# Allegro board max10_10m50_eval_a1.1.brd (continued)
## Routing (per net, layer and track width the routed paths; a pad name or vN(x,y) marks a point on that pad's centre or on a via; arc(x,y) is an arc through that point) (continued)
HDMI_VIDEO_DIN4: length 29.2
  TOP w0.147: U3.58 61.86,60.84 v2(62.36,61.34) ; U1.D12 v1(57.52,45.47)
  ART04 w0.109: v1(57.52,45.47) 57.52,45.86 57.02,46.35 57.02,46.74 57.53,47.24 57.53,53.86 57.65,53.98 59.95,53.98 60.07,54.09 60.07,54.37 59.95,54.48 57.65,54.48 57.53,54.6 57.53,54.87 57.65,54.99 60.08,54.99 60.2,55.11 60.2,61.09 61.47,62.36 62.1,62.36 62.36,62.1 v2(62.36,61.34)
HDMI_VIDEO_DIN5: length 29.6
  TOP w0.147: U3.57 60.23,61.35 59.42,60.53 59.4,60.53 58.93,60.06 58.93,56.89 59.31,56.52 60.96,56.52 61.34,56.13 61.34,54.74 62.61,53.47 65.91,53.47 66.04,53.59 66.04,54.46 66.19,54.61 66.53,54.61 66.67,54.46 66.67,53.47 67.18,52.96 67.18,50.8 66.42,50.04 61.98,50.04 61.51,49.58 61.51,47.46 U1.B16
HDMI_VIDEO_DIN6: length 29.5
  TOP w0.147: U1.A16 61.02,49.84 61.72,50.55 65.28,50.55 65.66,50.93 65.66,52.3 65.81,52.45 66.02,52.45 66.17,52.3 66.17,51.07 66.31,50.93 66.53,50.93 66.67,51.07 66.67,52.7 66.42,52.96 62.48,52.96 60.83,54.61 60.83,54.99 59.94,55.88 59.3,55.88 58.48,56.7 58.48,60.77 58.7,60.99 59.24,60.99 60.09,61.84 U3.56
HDMI_VIDEO_DIN7: length 32.6
  TOP w0.147: U1.C15 60.51,46.46 60.51,50.35 61.34,51.18 61.34,51.8 61.49,51.94 61.83,51.94 61.98,51.8 61.98,51.2 62.12,51.05 62.46,51.05 62.61,51.2 62.61,51.8 62.76,51.94 63.1,51.94 63.25,51.8 63.25,51.2 63.39,51.05 63.73,51.05 63.88,51.2 63.88,51.8 64.03,51.94 64.39,51.94 64.52,51.82 64.52,51.2 64.66,51.05 65,51.05 65.15,51.2 65.15,52.3 65,52.45 61.59,52.45 61.34,52.7 61.34,53.34 60.33,54.36 60.33,54.74 59.69,55.37 59.06,55.37 58.03,56.4 58.03,61.08 58.39,61.44 59.05,61.44 59.95,62.35 U3.55
HDMI_VIDEO_DIN8: length 28.9
  TOP w0.147: U1.B14 59.52,47.47 59.52,48.56 59.22,48.85 59.22,49.06 59.44,49.28 59.8,49.28 59.94,49.42 59.94,49.64 59.8,49.78 59.46,49.78 59.31,49.93 59.31,50.14 59.82,50.65 59.82,52.94 59.96,53.09 60.18,53.09 60.33,52.94 60.33,51.46 60.47,51.31 60.69,51.31 60.83,51.46 60.83,53.09 59.82,54.1 59.82,54.48 59.44,54.86 58.8,54.86 57.58,56.09 57.58,63.29 57.81,63.52 58.02,63.52 58.17,63.37 58.17,62.26 58.42,62 58.97,62 59.81,62.84 U3.54
HDMI_VIDEO_DIN9: length 26.5
  TOP w0.147: v2(58.8,64.14) 59.09,63.84 U3.52 ; U1.A14 v1(58.52,48.47)
  BOTTOM w0.147: v2(58.8,64.14) 56.28,64.14 56.13,63.99 56.13,63.65 56.28,63.5 57,63.5 57.15,63.35 57.15,63.01 57,62.86 56.28,62.86 56.13,62.72 56.13,62.38 56.28,62.23 57.02,62.23 57.53,61.72 58.8,61.72 58.93,61.59 58.93,61.21 58.8,61.09 58.04,61.09 57.78,60.83 57.78,49.2 v1(58.52,48.47)
HDMI_VIDEO_DIN10: length 28.4
  TOP w0.147: U1.A13 58.02,48.74 58.8,49.53 58.8,50.42 59.31,50.93 59.31,54.21 59.16,54.36 58.82,54.36 58.67,54.21 58.67,51.18 58.55,51.05 58.17,51.05 58.04,51.18 58.04,54.95 57.12,55.86 57.12,63.47 58.49,64.84 U3.50
HDMI_VIDEO_DIN11: length 30.7
  TOP w0.147: U3.49 64.08,65.35 64.26,65.53 64.26,65.79 64.14,65.91 59.94,65.91 59.44,65.41 58.29,65.41 56.67,63.78 56.67,55.6 57.52,54.75 57.52,50.43 57.67,50.28 58.15,50.28 58.29,50.14 58.29,49.84 58.15,49.69 57.67,49.69 57.52,49.55 57.52,47.47 U1.B12
HDMI_VIDEO_DIN12: length 29
  TOP w0.147: U1.A12 57.02,54.49 56.22,55.29 56.22,64.09 59.82,67.69 60.2,67.69 60.58,67.31 60.58,66.55 60.71,66.42 60.96,66.42 61.14,66.6 61.14,67.06 61.26,67.18 61.52,67.18 61.65,67.06 61.65,66.55 61.77,66.42 62.1,66.42 62.23,66.55 62.23,67.92 62.38,68.07 62.74,68.07 62.92,67.89 U3.48
HDMI_VIDEO_DIN13: length 31
  TOP w0.147: U1.C12 56.53,46.45 56.53,54.22 55.77,54.98 55.77,64.28 60.12,68.64 60.65,68.64 60.8,68.49 60.8,67.84 60.94,67.69 61.24,67.69 61.39,67.84 61.39,68.49 61.53,68.64 63.18,68.64 63.43,68.4 U3.47
HDMI_VIDEO_DIN14: length 28.8
  TOP w0.147: U1.A11 56.01,53.97 55.32,54.67 55.32,64.47 59.94,69.09 63.37,69.09 63.92,68.54 U3.46
HDMI_VIDEO_DIN15: length 31.5
  TOP w0.147: U3.45 64.43,68.67 64.38,68.72 64.38,68.72 63.56,69.54 59.75,69.54 59.48,69.28 54.86,64.66 54.86,64.28 54.86,54.36 55.52,53.7 55.52,47.46 U1.B11
HDMI_VIDEO_DIN16: length 31.8
  TOP w0.147: U3.44 64.92,68.81 64.88,68.85 64.88,68.86 64.83,68.91 64.83,68.91 63.75,69.99 59.53,69.99 54.36,64.82 54.36,54.1 55.01,53.44 U1.A10
HDMI_VIDEO_DIN17: length 27.3
  TOP w0.147: U1.C14 v1(58.52,46.47) ; v2(65.02,65.79) 65.43,66.19 U3.43
  BOTTOM w0.147: v1(58.52,46.47) 59.04,46.47 60.33,47.75 60.33,48.39 60.07,48.64 60.07,49.53 60.33,49.78 60.33,53.98 60.07,54.23 60.07,58.55 60.51,58.98 60.51,59.61 60.07,60.04 60.07,60.52 60.51,60.96 60.51,64.44 61.72,65.66 64.9,65.66 v2(65.02,65.79)
HDMI_VIDEO_DIN18: length 28.8
  TOP w0.147: v2(65.91,65.79) 65.91,66.13 65.92,66.15 U3.42 ; U1.E14 v1(59.52,44.47)
  BOTTOM w0.147: v2(65.91,65.79) 65.28,65.15 61.98,65.15 60.96,64.14 60.96,58.29 60.58,57.91 60.58,54.36 60.83,54.11 60.83,47.5 59.01,45.68 59.01,44.97 v1(59.52,44.47)
HDMI_VIDEO_DIN19: length 29.8
  TOP w0.147: U3.41 66.43,65.53 66.42,65.53 66.17,65.28 65.28,65.28 65.15,65.15 65.15,64.9 65.28,64.77 v2(65.91,64.77) ; U1.D14 v1(59.52,45.47)
  BOTTOM w0.147: v1(59.52,45.47) 60.02,45.97 60.83,45.97 61.09,46.23 61.09,47.04 61.47,47.42 61.47,54.12 61.09,54.5 61.09,57.66 61.42,58 61.42,63.84 62.23,64.64 65.79,64.64 v2(65.91,64.77)
HDMI_VIDEO_DIN20: length 30.1
  TOP w0.147: U3.40 66.92,66.01 66.93,66.01 v2(66.93,65.79) ; U1.C13 v1(57.52,46.47)
  BOTTOM w0.147: v2(66.93,65.79) 66.29,66.42 64.77,66.42 64.52,66.17 61.47,66.17 60.06,64.75 60.06,61.45 58.29,59.69 58.29,49.78 58.93,49.15 58.93,48.26 58.63,47.97 58.38,47.97 57.52,47.1 v1(57.52,46.47)
HDMI_VIDEO_DIN21: length 29.3
  TOP w0.147: U3.39 67.43,65.27 v2(66.93,64.77) ; U1.E15 v1(60.52,44.47)
  BOTTOM w0.147: v2(66.93,64.77) 66.29,64.14 62.48,64.14 61.88,63.53 61.88,57.77 61.59,57.49 61.59,54.78 62.01,54.36 62.01,45.38 61.6,44.97 61.02,44.97 v1(60.52,44.47)
HDMI_VIDEO_DIN22: length 30.2
  TOP w0.147: U1.F15 v1(60.52,43.47) ; v2(67.94,65.79) 67.92,65.81 U3.38
  ART04 w0.109: v1(60.52,43.47) 59.94,44.04 59.94,49.7 65.15,54.91 65.15,57.91 64.26,58.8 64.26,63.75 64.64,64.14 67.06,64.14 67.44,64.52 67.44,65.28 v2(67.94,65.79)
HDMI_VIDEO_DIN23: length 30.5
  TOP w0.147: v2(67.94,64.77) 68.43,65.25 U3.37 ; U1.D15 v1(60.52,45.47)
  ART04 w0.109: v2(67.94,64.77) 69.34,63.37 69.34,59.94 68.2,58.8 65.78,58.8 65.66,58.68 65.66,58.41 65.78,58.29 66.05,58.29 66.17,58.18 66.17,57.9 66.05,57.78 65.78,57.78 65.66,57.67 65.66,57.39 65.78,57.28 66.05,57.28 66.17,57.16 66.17,56.89 66.05,56.77 65.78,56.77 65.66,56.65 65.66,56.38 65.78,56.26 66.05,56.26 66.17,56.14 66.17,55.31 60.52,49.66 v1(60.52,45.47)
HDMI_VSYNC: length 31.3
  TOP w0.147: v2(62.87,53.98) 65.26,53.98 65.41,54.12 65.41,54.39 65.26,54.54 63.63,54.54 63.43,54.74 U3.2 ; U1.H14 v1(59.52,41.47)
  ART04 w0.109: v2(62.87,53.98) 63.5,53.98 64.64,55.12 64.64,57.67 64.53,57.78 64.25,57.78 64.14,57.67 64.14,55.37 63.37,54.61 62.74,54.61 62.36,54.23 62.36,52.83 59.44,49.91 59.44,45.97 59.05,45.59 59.05,41.66 59.25,41.47 v1(59.52,41.47)
I2C_MAXII_SCL: length 8.4
  TOP w0.147: v3(29.88,51.05) 30,50.93 U4.A7
  BOTTOM w0.147: R139.2 29.84,51.02 v3(29.88,51.05) 29.88,52.16 28.83,53.21 27.94,53.21 27.81,53.09 24.57,53.09 R206.1
I2C_MAXII_SDA: length 19.5
  TOP w0.147: v3(29.21,51.02) 29.5,50.73 U4.A6
  BOTTOM w0.147: R209.1 14.48,53.15 14.48,51.82 14.99,51.31 19.56,51.31 20.07,51.82 25.02,51.82 25.53,52.32 27.9,52.32 v3(29.21,51.02) 28.96,50.76 R137.2
JTAG_LOCK: length 27.6
  TOP w0.147: U4.Y8 30.23,40.7 v3(30.23,40.26) ; R151.2 v2(12.57,50.16)
  ART04 w0.109: v3(30.23,40.26) 29.59,40.26 27.81,42.04 27.81,44.45 26.42,45.85 26.16,45.85 25.91,46.1 25.91,46.86 23.62,49.15 23.62,49.4 21.97,51.05 17.02,51.05 15.49,49.53 15.49,49.15 15.11,48.77 13.72,48.77 13.34,49.15 13.34,49.4 v2(12.57,50.16)
JTAG_LOCK_R: length 9
  TOP w0.147: R151.1 5.71,50.16 4.45,48.89 J7.7
JTAG_SAFE: length 11.8
  TOP w0.147: U4.Y17 36.35,39.62 40.51,39.62 41.17,38.97 U1.K1
LPDDR2_CA0: length 19.5
  TOP w0.102: 77.6,38.34 79.33,38.34 U2.P3
  TOP w0.147: 77.6,38.34 77.36,38.34 77.09,38.61 74.95,38.61 74.8,38.46 74.8,38.12 74.95,37.97 76.81,37.97 76.96,37.83 76.96,37.49 76.81,37.34 74.68,37.34 74.17,37.85 74.17,38.35 73.28,39.24 69.09,39.24 68.37,39.97 U1.J22
LPDDR2_CA1: length 21.3
  TOP w0.102: 77.61,39.64 79.33,39.64 U2.N3
  TOP w0.137: U1.J21 66.52,40.47
  TOP w0.147: 66.52,40.47 68.75,40.47 69.47,39.75 71.99,39.75 72.14,39.9 72.14,40.24 71.99,40.39 69.74,40.39 69.6,40.53 69.6,40.87 69.74,41.02 72.39,41.02 74.34,39.07 77.04,39.07 77.61,39.64
LPDDR2_CA2: length 19.6
  TOP w0.102: U2.M3 79.33,40.29 79.33,40.83 79.23,40.94 77.6,40.94
  TOP w0.147: 77.6,40.94 77.38,41.15 75.69,41.15 74.42,42.42 74.42,46.23 73.91,46.74 72.64,46.74 71.88,45.97 70.02,45.97 U1.F22
LPDDR2_CA3: length 20.4
  TOP w0.102: U2.M2 78.68,40.29 77.75,40.29
  TOP w0.147: 77.75,40.29 76.73,40.29 76.58,40.13 75.06,40.13 73.26,41.93 73.26,43.2 72.9,43.56 72.26,43.56 72.01,43.31 70.74,43.31 70.53,43.52 70.53,43.73 70.74,43.94 71.63,43.94 71.84,44.16 71.84,44.36 71.63,44.58 70.48,44.58 67.37,41.47 66.52,41.47 U1.H21
LPDDR2_CA4: length 20.3
  TOP w0.147: U1.H22 67.64,40.97 69.47,42.8 72.52,42.8 72.64,42.67 72.64,42.31 72.5,42.16 69.62,42.16 69.47,42.02 69.47,41.68 69.62,41.53 72.77,41.53 74.68,39.62 76.83,39.62 77.17,39.96 U2.M1
LPDDR2_CA5: length 17.5
  TOP w0.102: U2.G2 78.68,42.88 77.6,42.88
  TOP w0.147: 77.6,42.88 77.13,42.88 75.44,44.58 75.44,47.88 75.18,48.13 70.18,48.13 U1.D22
LPDDR2_CA6: length 17.4
  TOP w0.102: U2.F2 78.68,43.53 77.6,43.53
  TOP w0.147: U1.C22 69.82,48.77 75.44,48.77 75.95,48.26 75.95,44.96 77.37,43.53 77.6,43.53
LPDDR2_CA7: length 20.2
  TOP w0.102: 77.6,42.09 78.11,41.59 79.23,41.59 79.33,41.69 79.33,43.53 U2.F3
  TOP w0.147: 77.6,42.09 77.27,42.42 76.93,42.42 74.93,44.41 74.93,47.24 74.68,47.5 72.39,47.5 71.63,46.74 69.79,46.74 U1.E22
LPDDR2_CA8: length 18.8
  TOP w0.102: 77.6,44.83 79.33,44.83 U2.E3
  TOP w0.147: U1.A21 67.96,49.91 76.07,49.91 76.96,49.02 76.96,45.47 77.6,44.83
LPDDR2_CA9: length 17.4
  TOP w0.102: U2.E2 78.68,44.18 77.6,44.18
  TOP w0.147: U1.B22 69.45,49.4 75.82,49.4 76.45,48.77 76.45,45.21 77.48,44.18 77.6,44.18
LPDDR2_CK: length 20.9
  TOP w0.102: U2.J3 v3(79.98,41.59)
  TOP w0.114: U1.D18 v1(63.52,44.47)
  BOTTOM w0.114: v1(63.52,44.47) 63.25,44.73 63.25,45.02 63.44,45.21 64.52,45.21 65.6,44.13 74.93,44.13 76.71,42.35 76.71,42.04 76.93,41.81 77.25,41.81 77.59,41.46 78.04,41.46 78.23,41.27 78.55,41.27 78.74,41.46 79,41.46 R33.2 79.48,41.08 v3(79.98,41.59)
LPDDR2_CKE: length 15.8
  TOP w0.147: U1.E21 v1(66.52,43.46) ; v2(75.31,42.42) 75.95,41.78 77.34,41.78 77.87,41.26 U2.K1
  BOTTOM w0.147: v1(66.52,43.46) 68.2,41.78 68.71,41.78 69.47,42.55 70.23,42.55 70.99,41.78 71.75,41.78 72.52,42.55 73.41,42.55 74.36,41.59 R31.2 75.31,41.72 v2(75.31,42.42)
LPDDR2_CKN: length 21.1
  TOP w0.102: U2.H3 v3(79.98,42.23)
  TOP w0.114: U1.E18 v1(62.52,44.46)
  BOTTOM w0.114: v3(79.98,42.23) 79.6,41.86 79.49,41.86 R33.1 79.18,41.78 77.73,41.78 75.06,44.45 65.73,44.45 64.65,45.53 63.31,45.53 62.93,45.15 62.93,44.88 v1(62.52,44.46)
LPDDR2_CSN: length 19.6
  TOP w0.147: U2.L1 75.47,40.61 73.84,42.24 73.84,45.92 73.66,46.1 73.41,46.1 73.22,45.91 73.22,44.32 73.09,44.2 72.64,44.2 72.52,44.32 72.52,44.96 72.33,45.14 70.19,45.14 U1.G22
LPDDR2_DM0: length 25.2
  TOP w0.147: U2.K5 80.23,40.54 80.23,36.83 v3(79.98,36.58) ; U1.N19 v1(64.52,35.46)
  ART04 w0.109: v1(64.52,35.46) 65.02,34.96 65.02,34.16 65.15,34.04 66.67,34.04 67.06,33.66 69.34,33.66 69.85,33.15 70.87,33.15 71.13,33.41 71.13,33.79 71.5,34.16 73.53,34.16 74.17,34.8 74.55,34.8 74.8,34.54 79.12,34.54 79.98,35.4 v3(79.98,36.58)
LPDDR2_DM1: length 27.5
  TOP w0.137: U1.J15 v1(60.52,40.47)
  TOP w0.147: U2.H5 80.5,43.01 v3(80.5,45.48)
  ART04 w0.109: v3(80.5,45.48) 80.15,45.13 77.72,45.13 77.52,45.34 68.07,45.34 66.75,44.02 66.24,44.02 66.04,43.81 66.04,43.31 65.82,43.09 64.18,43.09 63.89,42.8 63.89,42.29 63.37,41.77 63.37,41.4 62.83,40.86 62.32,40.86 61.98,40.51 61.98,40.13 61.85,40 60.98,40 v1(60.52,40.47)
LPDDR2_DQ0: length 23.7
  TOP w0.147: U1.N18 v1(63.52,35.46) ; U2.N8 v3(83.23,38.99)
  ART04 w0.109: v3(83.23,38.99) 83.23,38.53 82.8,38.1 81.79,38.1 81.03,37.34 79.63,37.34 78.11,35.81 72.9,35.81 72.39,35.31 70.61,35.31 70.23,34.92 69.85,34.92 69.47,35.31 69.09,35.31 68.71,34.92 68.33,34.92 67.82,35.43 66.08,35.43 65.67,35.84 63.89,35.84 v1(63.52,35.46)
LPDDR2_DQ1: length 24.7
  TOP w0.147: U2.M8 v3(83.23,39.64) ; U1.N20 v1(65.52,35.46)
  ART04 w0.102: 84.25,39.83 84.12,39.96 83.55,39.96 v3(83.23,39.64)
  ART04 w0.109: 84.25,39.83 84.25,38.86 82.04,36.65 81.08,36.65 80.77,36.96 79.88,36.96 78.23,35.31 73.15,35.31 72.52,34.67 71.37,34.67 70.97,34.27 67.46,34.27 66.8,34.92 66.05,34.92 v1(65.52,35.46)
LPDDR2_DQ2: length 24.2
  TOP w0.147: U2.M7 v3(82.58,39.64) ; U1.M20 v1(65.52,36.46)
  ART04 w0.109: v1(65.52,36.46) 65.94,36.46 66.31,36.09 67.69,36.09 67.88,36.28 72.1,36.28 72.73,36.92 76.54,36.92 76.71,37.08 76.71,37.34 76.83,37.46 77.09,37.46 77.22,37.34 77.22,37.04 77.34,36.92 78.06,36.92 78.21,37.06 78.21,37.23 78.11,37.34 77.72,37.34 77.6,37.46 77.6,37.97 77.72,38.1 78.11,38.1 78.23,38.23 78.23,38.51 78.36,38.63 78.61,38.63 78.74,38.51 78.74,38.1 78.87,37.97 79.12,37.97 79.25,38.1 79.25,38.51 79.38,38.63 79.63,38.63 79.76,38.51 79.76,38.35 79.86,38.25 80.16,38.25 80.26,38.35 80.26,38.61 80.39,38.73 81.28,38.73 81.41,38.86 81.41,39.12 81.51,39.22 82.17,39.22 v3(82.58,39.64)
LPDDR2_DQ3: length 27.4
  TOP w0.147: U1.M14 v1(59.52,36.46) ; U2.M9 v3(83.88,39.64)
  ART04 w0.102: 80.2,37.72 80.5,38.01 80.94,38.01 81.26,38.34 81.77,38.34 82.74,39.31 83.55,39.31 v3(83.88,39.64)
  ART04 w0.109: v1(59.52,36.46) 59.89,36.09 65.77,36.09 66.02,35.83 72.28,35.83 72.77,36.32 78.11,36.32 79.5,37.72 80.2,37.72
LPDDR2_DQ4: length 25.1
  TOP w0.147: U2.M6 v3(81.93,39.64) ; U1.M18 v1(63.52,36.46)
  ART04 w0.102: 80.9,38.99 80.01,38.99 79.64,39.36 78.48,39.36 78.1,38.99 77.72,38.99 77.34,38.61
  ART04 w0.109: v3(81.93,39.64) 81.55,39.64 80.9,38.99 ; v1(63.52,36.46) 63.05,36.46 62.94,36.58 62.94,36.83 63.07,36.96 67.69,36.96 67.94,36.7 71.88,36.7 72.01,36.83 72.01,37.21 72.52,37.72 72.86,37.72 73.24,37.34 73.41,37.34 73.53,37.46 73.53,37.85 73.62,37.93 73.95,37.93 74.04,37.85 74.04,37.46 74.17,37.34 74.42,37.34 74.55,37.46 74.55,37.85 74.64,37.93 74.97,37.93 75.06,37.85 75.06,37.46 75.18,37.34 75.44,37.34 75.82,37.72 76.45,37.72 77.34,38.61
LPDDR2_DQ5: length 26.5
  TOP w0.147: U2.L7 v3(82.58,40.29) ; U1.M15 v1(60.52,36.46)
  ART04 w0.102: 80.12,39.64 80.45,39.31 80.84,39.31 81.49,39.96 82.76,39.96 82.86,40.06 82.86,40.2 82.78,40.29 v3(82.58,40.29)
  ART04 w0.109: 80.12,39.64 77.49,39.64 76.96,39.12 76.96,38.86 76.45,38.35 72.39,38.35 71.17,37.13 67.92,37.13 67.82,37.24 62.39,37.24 62.23,37.08 62.23,36.83 62.12,36.72 61.96,36.72 61.85,36.83 61.85,36.97 61.73,37.08 61.56,37.08 60.94,36.46 v1(60.52,36.46)
LPDDR2_DQ6: length 22.9
  TOP w0.147: U2.L8 v3(83.23,40.29) ; U1.L20 v1(65.52,38.47)
  ART04 w0.102: 80.92,40.61 82.9,40.61 v3(83.23,40.29)
  ART04 w0.109: 80.92,40.61 80.9,40.64 76.83,40.64 76.2,40 75.82,40 75.69,39.88 75.31,39.88 75.18,40 74.94,40 74.56,39.62 74.3,39.62 74.17,39.75 74.17,39.95 74.04,40.08 73.79,40.08 73.66,39.95 73.66,39.75 73.53,39.62 73.28,39.62 73.15,39.75 73.15,39.96 73.04,40.08 72.77,40.08 72.64,39.95 72.64,39.75 72.52,39.62 72.26,39.62 72.14,39.75 72.14,39.95 72.01,40.08 71.75,40.08 71.63,39.95 71.63,39.75 71.5,39.62 71.25,39.62 71.12,39.75 71.12,39.95 70.99,40.08 70.74,40.08 70.61,39.95 70.61,39.75 70.48,39.62 70.23,39.62 70.1,39.75 70.1,39.88 69.98,40 69.72,40 69.47,39.75 68.96,39.75 68.1,38.89 66.34,38.89 65.91,38.47 v1(65.52,38.47)
LPDDR2_DQ7: length 24.6
  TOP w0.147: U2.L9 v3(83.88,40.29) ; U1.L18 v1(63.52,38.47)
  ART04 w0.109: v3(83.88,40.29) 84.35,40.29 84.45,40.39 84.45,40.77 84.33,40.89 83.82,40.89 83.69,40.77 83.44,40.77 83.31,40.89 81.92,40.89 81.53,41.27 80.9,41.27 80.56,40.94 79.8,40.94 79.76,40.89 76.58,40.89 76.2,40.51 69.09,40.51 67.82,39.24 66.29,39.24 65.89,38.84 64.67,38.84 64.67,38.84 64.24,38.84 63.87,38.47 v1(63.52,38.47)
LPDDR2_DQ8: length 25.1
  TOP w0.147: U1.K20 v1(65.52,39.47) ; U2.G9 v3(83.23,42.88)
  ART04 w0.102: 82.62,43.31 83.04,42.88 v3(83.23,42.88) ; 79.63,41.91 80.14,41.91 80.39,42.16 80.77,42.16 81.03,41.91 81.92,41.91 82.3,41.53 83.69,41.53 83.82,41.66 83.82,41.8 83.71,41.91 82.45,41.91 82.25,42.1 82.25,43.14
  ART04 w0.109: 82.25,43.14 82.42,43.31 82.62,43.31 ; v1(65.52,39.47) 66.05,40 67.06,40 68.58,41.53 75.95,41.53 76.16,41.74 77.17,41.74 77.32,41.59 79.31,41.59 79.63,41.91
LPDDR2_DQ9: length 25.4
  TOP w0.147: U1.K19 v1(64.52,39.47) ; U2.G8 v3(82.58,42.88)
  ART04 w0.102: 84.33,42.29 84.06,42.56 82.9,42.56 v3(82.58,42.88)
  ART04 w0.109: v1(64.52,39.47) 64.52,39.22 64.64,39.09 65.67,39.09 66.33,39.75 67.44,39.75 68.79,41.11 76.07,41.11 76.28,41.32 79.72,41.32 79.78,41.25 80.24,41.25 80.52,41.53 81.79,41.53 82.09,41.22 84.02,41.22 84.33,41.53 84.33,42.29
LPDDR2_DQ10: length 26.6
  TOP w0.147: U2.G7 v3(81.93,42.88) ; U1.K18 v1(63.52,39.47)
  ART04 w0.102: v3(81.93,42.88) 81.6,42.56 79.77,42.56 79.12,41.91 77.6,41.91
  ART04 w0.109: 77.6,41.91 77.34,42.16 75.82,42.16 75.61,41.95 74.76,41.95 74.68,42.04 74.68,42.35 74.55,42.48 74.3,42.48 74.17,42.35 74.17,42.04 74.08,41.95 73.75,41.95 73.66,42.04 73.66,42.35 73.53,42.48 73.28,42.48 73.15,42.35 73.15,42.04 73.07,41.95 72.73,41.95 72.64,42.04 72.64,42.35 72.52,42.48 72.26,42.48 72.14,42.35 72.14,42.04 72.05,41.95 71.71,41.95 71.63,42.04 71.63,42.35 71.5,42.48 71.25,42.48 71.12,42.35 71.12,42.04 71.03,41.95 70.69,41.95 70.61,42.03 70.61,42.35 70.48,42.48 70.23,42.48 70.1,42.35 70.1,42.04 70.03,41.96 69.67,41.96 69.59,42.04 69.59,42.3 69.41,42.48 68.89,42.48 66.81,40.4 66.05,40.4 65.66,40 64.52,40 64.06,39.54 64.06,39.24 63.84,39.03 63.61,39.03 63.52,39.12 v1(63.52,39.47)
LPDDR2_DQ11: length 26.1
  TOP w0.147: U1.H19 v1(64.52,41.47) ; U2.F6 v3(81.93,44.18)
  ART04 w0.102: v3(81.93,44.18) 82.14,44.18 82.27,44.31 82.27,44.45 82.14,44.58 81.03,44.58 80.9,44.45 80.9,44.2 80.77,44.07 80.52,44.07 80.39,44.2 80.39,44.45 80.26,44.58 79.76,44.58 79.63,44.45 79.63,44.2 79.5,44.07 79.38,44.07 79.25,44.2 79.25,44.45 79.12,44.58 78.97,44.58 78.87,44.48 78.87,44.2 78.74,44.07 78.59,44.07 78.49,44.17 78.49,44.48 78.38,44.58 78.23,44.58 78.11,44.45 78.11,44.29 78,44.18 77.5,44.18
  ART04 w0.109: 77.5,44.18 77.38,44.07 69.22,44.07 68.83,44.45 68.45,44.45 68.07,44.07 68.07,43.81 67.94,43.69 67.56,43.69 67.31,43.43 67.31,43.05 66.17,41.91 65.41,41.91 65.15,42.16 64.82,42.16 64.52,41.86 64.21,41.86 63.88,41.53 63.88,41.02 64.01,40.89 64.14,40.89 64.52,41.27 v1(64.52,41.47)
LPDDR2_DQ12: length 25
  TOP w0.147: U1.H20 v1(65.52,41.47) ; U2.F9 v3(83.23,43.53)
  ART04 w0.102: 77.27,43.53 78.08,43.53 78.4,43.86 82.4,43.86 83.05,43.21 84.58,43.21 84.84,43.46 84.84,44.32 84.65,44.51 84.4,44.51 84.21,44.32 84.21,43.99 84.07,43.86 83.74,43.86 83.41,43.53 v3(83.23,43.53)
  ART04 w0.109: 77.27,43.53 77.22,43.59 68.41,43.59 68.17,43.35 66.29,41.47 v1(65.52,41.47)
LPDDR2_DQ13: length 27.6
  TOP w0.147: v1(62.52,41.47) 62.52,41.46 U1.H18 ; U2.F7 v3(82.58,44.18)
  ART04 w0.102: 77.62,46.46 82.06,46.46 82.25,46.27 82.25,46 83.55,44.7 83.55,44.05 83.36,43.86 82.9,43.86 v3(82.58,44.18)
  ART04 w0.109: 77.62,46.46 68.05,46.46 66.55,44.96 65.66,44.96 64.77,44.07 64.14,44.07 62.91,42.84 62.91,41.86 v1(62.52,41.47)
LPDDR2_DQ14: length 28.7
  TOP w0.147: U1.J14 v1(59.52,40.47) ; U2.F8 v3(83.23,44.18)
  ART04 w0.102: 77.6,45.81 82.08,45.81 83.23,44.66 v3(83.23,44.18)
  ART04 w0.109: 77.6,45.81 68.03,45.81 66.68,44.45 65.76,44.45 65.15,43.84 64.36,43.84 63.14,42.62 63.14,41.56 62.67,41.09 60.49,41.09 59.86,40.47 v1(59.52,40.47)
LPDDR2_DQ15: length 27.7
  TOP w0.147: U1.J18 v1(63.52,40.47) ; U2.E8 v3(82.58,44.83)
  ART04 w0.109: v3(82.58,44.83) 82.3,44.83 82.17,44.97 82.17,45.34 82.04,45.47 81.79,45.47 81.66,45.34 81.66,44.97 81.53,44.84 77.56,44.84 77.29,44.58 76.81,44.58 76.7,44.69 76.7,44.8 76.58,44.92 76.35,44.92 76.23,44.8 76.23,44.69 76.11,44.58 75.88,44.58 75.76,44.69 75.76,44.8 75.65,44.92 75.41,44.92 75.3,44.8 75.3,44.69 75.18,44.58 74.94,44.58 74.83,44.69 74.83,44.8 74.71,44.92 74.48,44.92 74.36,44.8 74.36,44.69 74.24,44.58 74.01,44.58 73.89,44.69 73.89,44.8 73.78,44.92 73.54,44.92 73.43,44.8 73.43,44.69 73.31,44.58 73.08,44.58 72.96,44.69 72.96,44.8 72.84,44.92 72.61,44.92 72.49,44.8 72.49,44.69 72.37,44.58 72.14,44.58 72.02,44.69 72.02,44.8 71.91,44.92 71.67,44.92 71.56,44.8 71.56,44.69 71.44,44.58 71.21,44.58 71.09,44.69 71.09,44.8 70.97,44.92 70.74,44.92 70.62,44.8 70.62,44.69 70.5,44.58 70.27,44.58 70.15,44.69 70.15,44.8 70.04,44.92 69.8,44.92 69.69,44.8 69.69,44.69 69.57,44.58 69.34,44.58 69.22,44.69 69.22,44.8 69.1,44.92 68.29,44.92 66.93,43.56 66.93,43.31 66.46,42.84 64.3,42.84 64.14,42.67 64.14,42.16 63.63,41.66 63.63,41.15 63.52,41.04 v1(63.52,40.47)
LPDDR2_DQS0: length 26.6
  TOP w0.114: U2.L6 v3(81.28,40.29) ; U1.L14 v1(59.52,38.47)
  ART04 w0.084: v3(81.28,40.29) 80.95,39.96 77.17,39.96 76.07,38.86 71.66,38.86 71.5,38.7 71.5,38.35 71.12,37.97 70.48,37.97 70.1,38.35 70.1,38.7 69.98,38.82 69.05,38.82 67.82,37.59 61.5,37.59 60.82,36.91 60.12,36.91 59.82,37.21 59.82,38.16 v1(59.52,38.47)
LPDDR2_DQS0N: length 26.5
  TOP w0.114: U2.L5 v3(80.63,40.29) ; U1.L15 v1(60.52,38.47)
  ART04 w0.084: v3(80.63,40.29) 77.08,40.29 75.95,39.15 75.56,39.15 75.35,39.37 75.06,39.37 74.84,39.15 71.54,39.15 71.21,38.82 71.21,38.48 71,38.27 70.61,38.27 70.4,38.48 70.4,38.82 70.1,39.12 68.93,39.12 67.7,37.88 66.67,37.88 66.46,38.1 66.17,38.1 65.95,37.88 65.6,37.88 65.38,38.1 65.11,38.1 64.9,37.88 64.52,37.88 64.3,38.1 64.01,38.1 63.79,37.88 63.41,37.88 63.19,38.1 62.99,38.1 62.78,37.88 62.36,37.88 62.14,38.1 61.85,38.1 61.63,37.88 61.38,37.88 60.7,37.2 60.24,37.2 60.11,37.33 60.11,38.06 v1(60.52,38.47)
LPDDR2_DQS1: length 26.6
  TOP w0.114: U1.K14 v1(59.52,39.47) ; U2.G6 v3(81.93,43.53)
  ART04 w0.084: v3(81.93,43.53) 81.6,43.21 79.91,43.21 79.5,42.8 79.09,42.8 78.82,43.07 78.55,43.07 78.07,42.58 76.71,42.58 76.41,42.89 68.7,42.89 66.65,40.84 64.91,40.84 63.92,39.84 63.28,39.84 63.14,39.7 63.14,39.04 62.94,38.85 60.13,38.85 v1(59.52,39.47)
LPDDR2_DQS1N: length 26.9
  TOP w0.114: U1.K15 v1(60.52,39.47) ; U2.G5 v3(81.28,43.53)
  ART04 w0.084: v3(81.28,43.53) 81.24,43.5 79.79,43.5 79.38,43.09 79.21,43.09 78.94,43.36 78.43,43.36 77.95,42.88 76.83,42.88 76.53,43.18 68.58,43.18 66.49,41.09 64.75,41.09 63.75,40.09 63.17,40.09 62.89,39.81 62.89,39.19 62.8,39.09 62.25,39.09 62.1,39.24 61.85,39.24 61.7,39.09 61.36,39.09 61.21,39.24 60.86,39.24 60.71,39.09 60.25,39.09 59.94,39.4 59.94,39.75 60.07,39.88 60.39,39.88 60.52,39.75 v1(60.52,39.47)
LPDDR2_VREFCA: length 6.4
  TOP w0.305: U2.G3 80.14,43.69 80.14,44.03 v3(79.98,44.18)
  BOTTOM w0.406: R29.1 C241.2 R32.2 C10.1 79.38,45.78 79.38,44.79 v3(79.98,44.18)
LPDDR2_VREFDQ: length 4
  TOP w0.305: U2.J9 v3(83.88,42.23)
  BOTTOM w0.406: C242.2 85.98,41.34 85.92,41.27 R34.2 85.47,41.34 R30.1 C11.1 84.57,42.23 v3(83.88,42.23)
LPDDR2_ZQ: length 1.5
  TOP w0.305: U2.D3 v3(79.98,45.48)
  BOTTOM w0.305: v3(79.98,45.48) 79.98,45.12 80.26,44.83 R35.1
MAX10_BYPASSN: length 14.2
  TOP w0.147: v3(37.08,50.67) 37.08,50.25 36.8,49.97 U4.B20 ; SW2.5 45.72,53.72 46.23,53.21 R192.2 46.16,52.07 v2(44.96,52.07)
  ART04 w0.109: v3(37.08,50.67) 37.59,51.18 44.07,51.18 v2(44.96,52.07)
MAX10_CONF_DONE: length 31.6
  TOP w0.147: U4.U13 33,42.78 33.15,42.93 33.15,43.43 33.4,43.69 v3(33.91,43.69) ; U1.F8 v1(52.51,43.47)
  ART04 w0.102: 37.34,42.67 36.58,42.67
  ART04 w0.109: 36.58,42.67 35.05,44.2 34.42,44.2 v3(33.91,43.69) ; 37.34,42.67 41.66,42.67 42.29,42.04 44.07,42.04 45.85,40.26 48.66,40.26 49.26,40.86 49.69,40.86 49.78,40.77 50.16,40.77 50.29,40.89 50.55,40.89 50.89,41.24 50.89,42.76 51.05,42.93 51.53,42.93 52.07,43.47 v1(52.51,43.47)
  BOTTOM w0.147: R28.2 51,47.74 51,45.14 51.18,44.96 51.82,44.96 52.01,44.76 52.01,43.97 v1(52.51,43.47)
MAX10_CONFIG_SEL: length 25.3
  TOP w0.147: SW2.6 45.09,56.52 44.7,56.13 44.7,53.21 v2(44.32,52.83) 44.2,52.7 R191.2 ; U1.H10 v1(54.51,40.47)
  BOTTOM w0.102: 49.15,46.86 49.15,44.33 49.41,44.07 49.63,44.07 50.04,43.66 50.04,42.42 50.64,41.82 52.9,41.82 54.08,40.64 54.34,40.64 v1(54.51,40.47)
  BOTTOM w0.147: 49.15,46.86 49.15,46.99 49.02,47.12 49.02,49.02 47.2,50.84 45.43,50.84 44.32,51.94 v2(44.32,52.83)
MAX10_JTAG_TCK: length 22
  TOP w0.147: v3(35.56,51.56) 35.09,51.56 U4.A15 ; U1.G2 47.51,42.46 v1(47.51,42.47)
  BOTTOM w0.147: v3(35.56,51.56) 37.97,51.56 38.35,51.18 42.93,51.18 43.94,50.16 43.94,47.62 45.21,46.35 45.21,42.8 45.4,42.61 R23.2 46.67,42.61 46.82,42.47 v1(47.51,42.47)
MAX10_JTAG_TDI: length 27
  TOP w0.147: U4.A13 33,50.65 v3(33.78,51.43) ; U1.L4 v1(48.51,38.47)
  BOTTOM w0.147: v3(33.78,51.43) 36.7,48.51 36.7,44.32 38.48,42.55 38.48,40.26 38.73,40 41.02,40 41.27,40.26 42.8,40.26 42.99,40.07 R25.2 46.86,39.62 47.12,39.88 47.75,39.88 48.01,39.62 48.01,39.37 48.39,38.99 48.39,38.59 v1(48.51,38.47)
MAX10_JTAG_TDO: length 20.1
  TOP w0.147: U4.A12 32.5,50.79 v3(33.15,51.43)
  BOTTOM w0.147: v3(33.15,51.43) 33.15,51.18 36.07,48.26 36.07,42.04 37.21,40.89 37.21,39.5 37.97,38.73 41.53,38.73 41.66,38.61 R314.1
MAX10_JTAG_TDO_3V3: length 9.9
  TOP w0.147: U1.M5 v1(50.51,36.47)
  BOTTOM w0.147: v1(50.51,36.47) 50.02,36.96 48.77,36.96 48.01,37.72 48.01,38.58 47.73,38.86 46.99,38.86 46.86,38.99 44.32,38.99 43.94,38.61 R314.2
MAX10_JTAG_TMS: length 20.6
  TOP w0.147: U4.A16 34.83,50.8 35.56,50.8 35.81,51.05 v3(36.32,51.05) ; U1.H2 46.51,41.47 43.12,41.47 v2(43.05,41.53)
  BOTTOM w0.147: v3(36.32,51.05) 37.19,51.05 38.1,50.14 38.1,48.77 38.35,48.51 38.35,44.7 40.26,42.8 41.78,42.8 42.35,42.23 R24.2 42.93,41.4 v2(43.05,41.53)
MAX10_JTAGEN: length 31.4
  TOP w0.147: v1(52.53,38.48) 53.53,38.48 U1.K9 ; U4.A14 33.5,50.52 v3(34.42,51.43)
  BOTTOM w0.147: v3(34.42,51.43) 34.8,51.43 36.39,49.85 37.27,49.85 37.47,49.66 37.47,44.7 39.12,43.05 39.12,40.77 39.31,40.58 R21.2 R22.2 40.96,40.58 41.15,40.77 43.37,40.77 43.88,40.26 46.35,40.26 46.48,40.39 48.77,40.39 49.16,39.99 51.7,39.99 52.07,39.62 52.07,38.94 v1(52.53,38.48)
MAX10_NCONFIG: length 58.5
  TOP w0.147: U1.H9 v1(54.51,41.47) ; S6.3 45.72,17.63 45.47,17.38 42.06,17.38 41.81,17.63 S6.4 38.86,18.32 38.86,19.18 37.85,20.19 37.85,20.83 36.45,22.23 33.15,22.23 v1(32.64,22.73)
  ART04 w0.109: v1(32.64,22.73) 33.4,22.73 36.07,25.4 36.07,38.86 36.96,39.75 44.96,39.75 45.21,39.5 46.61,39.5 47.03,39.07 51.77,39.07 52.07,39.37 52.07,39.75 53.78,41.47 v1(54.51,41.47)
  BOTTOM w0.147: R203.2 56.07,41.59 55.7,41.97 55.01,41.97 v1(54.51,41.47)
MAX10_NSTATUS: length 31.4
  TOP w0.147: U1.G9 v1(53.51,42.47) ; v3(34.54,43.31) 34.54,42.8 34.5,42.76 U4.U16
  ART04 w0.109: v3(34.54,43.31) 37.59,40.26 45.34,40.26 45.76,39.84 51.53,39.84 53.51,41.83 v1(53.51,42.47)
  BOTTOM w0.147: R27.2 51.56,48.07 51.56,46.23 52.07,45.72 52.07,45.21 52.32,44.96 52.83,44.96 52.96,44.83 52.96,44.07 53.09,43.94 53.72,43.94 53.98,43.69 53.98,42.93 v1(53.51,42.47)
MAX10_RDN: length 3.6
  TOP w0.147: U1.U17 v1(62.52,32.46)
  BOTTOM w0.147: R8.2 62.17,30.99 62.74,30.99 62.99,31.24 62.99,31.99 v1(62.52,32.46)
MAX10_RESETN: length 69.2
  TOP w0.147: v2(29.72,22.1) 29.27,22.1 R204.2 28.77,21.15 29.21,20.7 29.21,19.81 29.9,19.12 S7.4 29.9,17.38 31.9,17.38 32.77,16.51 35.43,16.51 36.55,17.63 S7.3 ; v1(54.51,45.47) 54.51,45.46 U1.D9
  ART04 w0.109: v1(54.51,45.47) 54.99,44.99 54.99,44.2 54.64,43.84 52.17,43.84 51.94,44.07 50.42,44.07 50.04,43.69 50.04,41.46 49.67,41.09 49.33,41.09 49.15,41.27 48.9,41.27 48.26,40.64 46.1,40.64 44.2,42.55 42.42,42.55 41.78,43.18 37.97,43.18 36.32,44.83 33.91,44.83 33.15,44.07 33.15,43.05 35.56,40.64 35.56,35.43 34.54,34.42 34.54,25.27 32.26,22.99 30.61,22.99 v2(29.72,22.1)
MAX10_RUP: length 5.6
  TOP w0.147: U1.U18 v1(63.52,31.46)
  BOTTOM w0.147: v1(63.52,31.46) 64.01,31.96 64.01,32.77 64.2,32.96 67.06,32.96 R7.2
MAX_SDA: length 1.8
  TOP w0.147: U4.C1 26.48,49.47 v3(26.42,49.53)
  BOTTOM w0.147: v3(26.42,49.53) 26.86,49.09 R123.2
MAXII_CONF_DONE: length 3.7
  TOP w0.147: D8.2 30.58,37.77 31.12,38.31 31.12,40.26 31.5,40.64 U4.Y10
MAXII_CONF_DONE_R: length 1.3
  TOP w0.147: R194.2 D8.1
MIPI_TX_CLK24MHZ: length 72
  ART04 w0.109: v2(3.81,58.8) 3.81,46.99 6.73,44.07 7.24,44.07 9.78,41.53 9.78,37.59 14.35,33.02 14.35,26.03 14.99,25.4 17.14,25.4 17.4,25.15 19.69,25.15 20.96,23.88 22.48,23.88 23.37,24.77 25.4,24.77 26.29,23.88 26.29,21.46 26.67,21.08 v2(29.72,21.08)
  BOTTOM w0.147: R212.2 13.46,56.32 13.46,57.02 12.06,58.42 4.19,58.42 v2(3.81,58.8) ; v2(29.72,21.08) 29.72,21.44 29.93,21.65 J1.11
MIPI_TX_CLK24MHZ_R: length 1.9
  BOTTOM w0.147: R212.1 16.39,54.74 16.65,55 U14.21
MIPI_TX_CLK_HS_N: length 6.3
  TOP w0.132: R42.2 41.92,32.46 42.09,32.46 TP10.1 42.87,32.33 43.12,32.33 43.56,32.77 43.56,33.55 44.04,34.03 44.83,34.03 44.95,33.91 45.22,33.91 45.34,34.03 45.95,34.03 U1.R1
MIPI_TX_CLK_HS_P: length 7
  TOP w0.132: U1.R2 46.51,34.46 43.86,34.46 43.12,33.73 43.12,32.95 42.94,32.77 42.67,32.77 TP8.1 R41.2
MIPI_TX_CLK_LP_N: length 9.6
  TOP w0.147: U1.Y1 v1(45.51,28.46)
  BOTTOM w0.147: R47.2 TP11.1 42.8,31.75 42.8,30.86 43.81,29.84 43.81,28.83 44.32,28.32 44.68,28.32 44.83,28.47 44.83,28.7 44.43,29.11 44.43,29.31 44.6,29.49 44.94,29.49 45.51,28.91 v1(45.51,28.46)
MIPI_TX_CLK_LP_P: length 9.8
  TOP w0.147: U1.Y2 v1(46.51,28.46)
  BOTTOM w0.147: v1(46.51,28.46) 46.51,28.1 46.35,27.94 46.1,27.94 46,28.04 46,29.44 45.34,30.1 44.45,30.1 43.31,31.24 43.31,32.46 42.87,32.89 TP7.1 R37.2
MIPI_TX_CLKN: length 17.4
  TOP w0.132: v1(32.51,28.83) 32.61,28.93 33.07,28.93 33.55,28.45 34.42,28.45 35.05,29.08 35.05,31.12 35.94,32 35.94,33.29 36.3,33.66 37.36,33.66 38.81,32.2 39.3,32.2 v1(39.62,31.88) 39.99,32.24 40.34,32.24 R42.1
  BOTTOM w0.132: R43.2 38.9,32.23 39.27,32.23 v1(39.62,31.88) 39.98,32.23 40.35,32.23 R42.1 ; J1.25 31.16,28.83 v1(32.51,28.83)
MIPI_TX_CLKP: length 17.4
  TOP w0.132: R41.1 40.36,32.68 39.96,32.68 v1(39.62,33.02) 39.24,32.64 38.99,32.64 37.54,34.09 36.12,34.09 35.5,33.47 35.5,32.18 34.62,31.3 34.62,29.26 34.24,28.88 33.73,28.88 33.25,29.36 32.61,29.36 v1(32.51,29.46)
  BOTTOM w0.132: R41.1 40.35,32.67 39.98,32.67 v1(39.62,33.02) 39.27,32.67 38.9,32.67 R38.1 ; J1.26 33.54,28.91 33.07,28.91 v1(32.51,29.46)
MIPI_TX_CMOS_RST_1V8: length 22.5
  TOP w0.147: U1.T3 47.52,33.46 v1(47.51,33.46)
  ART04 w0.109: v2(42.29,21.46) 42.29,29.84 45.91,33.46 v1(47.51,33.46)
  BOTTOM w0.147: v2(42.29,21.46) R308.2 40.83,21.91 40.45,22.29 R312.2
MIPI_TX_CMOS_RST_3V3: length 57.3
  TOP w0.147: U1.B10 v1(55.52,46.46)
  ART04 w0.109: v3(32.64,51.43) 33.15,50.93 35.56,50.93 36.2,50.29 47.12,50.29 48.77,51.94 50.67,51.94 v2(50.93,51.69)
  BOTTOM w0.147: R309.2 32.7,51.82 32.64,51.75 v3(32.64,51.43) 32.64,50.8 35.43,48.01 35.43,43.43 34.42,42.42 34.42,37.59 36.32,35.69 36.32,26.42 35.88,25.97 R313.2 ; v2(50.93,51.69) 51.56,51.69 53.47,49.78 53.47,49.15 55.52,47.1 v1(55.52,46.46)
MIPI_TX_CMOS_RST_IO: length 4.9
  BOTTOM w0.147: J1.14 35.56,23.15 35.59,23.18 R312.1 36.7,23.68 C28.1 36.77,24.33 R313.1
MIPI_TX_CMOS_SCLK: length 4.7
  BOTTOM w0.147: R294.1 37.78,21.46 37.72,21.4 R302.1 37.02,21.59 35.43,21.59 34.87,22.15 J1.12
MIPI_TX_CMOS_SCLK_1V8: length 22.6
  TOP w0.147: U1.N3 v1(47.51,36.46)
  ART04 w0.109: v1(47.51,36.46) 46.99,35.94 46.99,35.31 41.66,29.97 41.66,22.48 v2(38.99,19.81)
  BOTTOM w0.147: v2(38.99,19.81) 39.05,19.88 R68.2 R294.2
MIPI_TX_CMOS_SCLK_3V3: length 40.2
  TOP w0.147: U1.J11 v1(55.51,39.46)
  ART04 w0.109: v1(55.51,39.46) 55.04,38.99 53.59,38.99 52.69,38.09 46.62,38.09 45.97,38.73 37.34,38.73 36.96,38.35 36.96,36.58 37.59,35.94 37.59,22.1 v2(36.45,20.95)
  BOTTOM w0.147: R303.2 R302.2 36.89,20.51 v2(36.45,20.95)
MIPI_TX_CMOS_SDATA: length 3.5
  BOTTOM w0.147: R304.1 R307.1 29.57,22.65 J1.13
MIPI_TX_CMOS_SDATA_1V8: length 32.1
  TOP w0.147: U1.N2 v1(46.51,35.46)
  ART04 w0.109: v1(46.51,35.46) 45.88,35.46 40.89,30.48 40.89,22.86 37.85,19.81 35.84,19.81 35.33,20.32 34.92,20.32 34.16,19.56 29.21,19.56 v2(28.7,20.07)
  BOTTOM w0.147: R307.2 v2(28.7,20.07) 28.7,19.57 28.64,19.5 R305.2
MIPI_TX_CMOS_SDATA_3V3: length 48.4
  TOP w0.147: v1(56.51,40.47) 56.52,40.47 U1.H12
  ART04 w0.109: v1(56.51,40.47) 56.05,40 53.21,40 52.96,39.75 52.96,39.24 52.7,38.99 52.2,38.99 52.05,38.84 46.5,38.84 46.23,39.12 44.45,39.12 44.32,39.24 37.08,39.24 36.45,38.61 36.45,24.89 33.15,21.59 v2(26.92,21.59)
  BOTTOM w0.147: v2(26.92,21.59) R306.2 R304.2
MIPI_TX_DATA1N: length 17
  TOP w0.132: v1(32.51,30.48) 32.61,30.58 33.12,30.58 33.53,30.99 33.53,31.62 34.29,32.38 34.29,33.13 33.53,33.89 33.53,34.42 34.01,34.9 39.27,34.9 v1(39.62,34.54) 39.98,34.9 40.35,34.9 R54.1
  BOTTOM w0.132: J1.28 33.61,29.97 32.79,29.97 32.51,30.25 v1(32.51,30.48) ; R55.2 38.97,34.85 39.32,34.85 v1(39.62,34.54) 39.98,34.9 40.35,34.9 R54.1
MIPI_TX_DATA1P: length 17
  TOP w0.132: v1(32.51,31.12) 32.61,31.02 32.94,31.02 33.09,31.17 33.09,31.8 33.85,32.57 33.85,32.95 33.09,33.71 33.09,34.6 33.83,35.33 39.27,35.33 v1(39.62,35.69) 39.98,35.33 40.35,35.33 R50.1
  BOTTOM w0.132: R51.1 38.82,35.28 39.22,35.28 v1(39.62,35.69) 39.98,35.33 40.35,35.33 R50.1 ; v1(32.51,31.12) 32.05,30.65 J1.29
MIPI_TX_DATA2N: length 15.2
  TOP w0.132: v1(32.51,27.05) 32.61,27.15 35.79,27.15 36.45,27.81 36.45,29.61 37.32,30.48 37.98,30.48 38.81,29.65 39.18,29.65 v1(39.62,29.21) 39.98,29.56 40.36,29.56 40.58,29.34 R65.1
  BOTTOM w0.132: R66.2 38.9,29.56 39.27,29.56 v1(39.62,29.21) 39.98,29.56 40.35,29.56 R65.1 ; J1.22 33.6,27.33 32.79,27.33 v1(32.51,27.05)
MIPI_TX_DATA2P: length 15.2
  TOP w0.132: v1(32.51,27.69) 32.61,27.59 35.61,27.59 36.01,27.99 36.01,29.79 37.14,30.92 38.16,30.92 38.99,30.09 39.36,30.09 v1(39.62,30.35) 39.98,30 40.36,30 40.58,30.22 R62.1
  BOTTOM w0.132: J1.23 32.48,27.65 v1(32.51,27.69) ; R63.1 38.9,30 39.27,30 v1(39.62,30.35) 39.98,30 40.35,30 R62.1
MIPI_TX_DATA3N: length 13.8
  TOP w0.132: R44.1 40.4,27.38 39.93,27.38 v1(39.62,27.69) 39.29,27.36 38.66,27.36 38.17,26.87 38.17,26.09 37.92,25.84 37.65,25.84 37.29,26.19 32.61,26.19 v1(32.51,26.29)
  BOTTOM w0.132: R45.2 38.9,27.33 39.27,27.33 v1(39.62,27.69) 39.98,27.33 40.35,27.33 R44.1 ; J1.19 31.87,25.65 v1(32.51,26.29)
MIPI_TX_DATA3P: length 13.9
  TOP w0.132: R40.1 40.3,26.95 40.03,26.95 v1(39.62,26.54) 39.25,26.92 38.84,26.92 38.61,26.69 38.61,25.91 38.1,25.4 37.47,25.4 37.11,25.75 32.61,25.75 v1(32.51,25.65)
  BOTTOM w0.132: v1(32.51,25.65) 33.27,26.42 33.52,26.42 J1.20 ; R40.1 40.35,26.9 39.98,26.9 v1(39.62,26.54) 39.27,26.9 38.9,26.9 R39.1
MIPI_TX_DATA4N: length 12.5
  TOP w0.132: v1(32.51,24) 32.61,24.1 38.61,24.1 38.79,24.28 39.22,24.28 v1(39.62,23.88) 39.95,24.2 40.38,24.2 R56.1
  BOTTOM w0.132: R56.1 40.35,24.23 39.98,24.23 v1(39.62,23.88) 39.27,24.23 38.9,24.23 R57.2 ; v1(32.51,24) 32.89,24.38 33.55,24.38 J1.16
MIPI_TX_DATA4P: length 12.5
  TOP w0.132: R53.1 40.32,24.64 40.01,24.64 v1(39.62,25.02) 39.32,24.72 38.6,24.72 38.43,24.54 32.61,24.54 v1(32.51,24.64)
  BOTTOM w0.132: R52.1 38.9,24.67 39.27,24.67 v1(39.62,25.02) 39.98,24.67 40.35,24.67 R53.1 ; v1(32.51,24.64) 31,24.64 J1.17
MIPI_TX_DATA_HS_N1: length 6.7
  TOP w0.132: R54.2 41.66,34.87 42.35,34.87 TP15.1 42.72,34.85 43.25,34.85 43.69,35.28 43.69,36.07 43.94,36.32 44.45,36.32 44.78,36 44.78,35.49 45.3,34.96 U1.P1
MIPI_TX_DATA_HS_N2: length 8.3
  TOP w0.132: U1.T1 46.01,32.59 45.81,32.38 45.59,32.38 45.47,32.51 45.47,32.91 45.35,33.03 44.84,33.03 44.58,32.77 44.58,32 43.56,30.99 43.56,29.97 43.15,29.56 42.77,29.56 TP21.1 42.24,29.64 41.77,29.64 R65.2
MIPI_TX_DATA_HS_N3: length 8
  TOP w0.132: R44.2 41.74,27.28 42.27,27.28 TP27.1 42.77,27.33 43.08,27.33 43.51,27.76 43.51,29.14 44.27,29.9 44.27,30.66 45.18,31.57 45.62,31.57 U1.U1
MIPI_TX_DATA_HS_N4: length 9.7
  TOP w0.132: U1.W1 46.37,29.96 46.46,29.88 46.46,29.59 46.33,29.46 45.81,29.46 45.06,28.71 45.06,27.03 43.62,25.58 43.62,24.81 43.06,24.26 42.8,24.26 TP33.1 42.32,24.23 41.69,24.23 R56.2
MIPI_TX_DATA_HS_P1: length 7.2
  TOP w0.132: R50.2 41.72,35.31 42.29,35.31 TP14.1 42.82,35.29 43.07,35.29 43.25,35.46 43.25,36.25 43.76,36.76 44.63,36.76 45.21,36.18 45.21,35.67 45.48,35.4 45.71,35.4 46.01,35.71 U1.N1
MIPI_TX_DATA_HS_P2: length 8.5
  TOP w0.132: U1.T2 46.51,33.46 44.66,33.46 44.14,32.95 44.14,32.18 43.12,31.17 43.12,30.15 42.97,30 42.77,30 TP20.1 42.4,30.08 41.62,30.08 R62.2
MIPI_TX_DATA_HS_P3: length 7.9
  TOP w0.132: R40.2 41.64,26.85 42.37,26.85 TP26.1 42.77,26.9 43.26,26.9 43.94,27.58 43.94,28.96 44.7,29.72 44.7,30.48 45.36,31.14 45.84,31.14 U1.V1
MIPI_TX_DATA_HS_P4: length 10.1
  TOP w0.132: R53.2 41.69,24.67 42.32,24.67 TP32.1 42.74,24.69 42.88,24.69 43.18,24.99 43.18,25.76 44.62,27.21 44.62,28.86 45.47,29.7 45.47,30.16 45.77,30.46 46.51,30.46 U1.W2
MIPI_TX_DATA_LP_N1: length 14.1
  TOP w0.147: U1.V4 v1(49.52,30.46)
  BOTTOM w0.147: R58.2 TP16.1 42.8,34.42 42.8,33.78 43.05,33.53 43.56,33.53 43.81,33.27 43.81,31.5 44.58,30.73 45.59,30.73 46.23,30.1 46.61,30.1 46.74,30.23 46.74,30.73 46.97,30.97 49.91,30.97 50.04,30.84 50.04,30.63 49.88,30.46 v1(49.52,30.46)
MIPI_TX_DATA_LP_N2: length 8.9
  TOP w0.147: U1.AB2 v1(46.52,26.47)
  BOTTOM w0.147: v1(46.52,26.47) 45.85,25.8 45.85,25.53 45.59,25.27 45.21,25.27 44.96,25.53 44.96,26.03 42.8,28.19 42.8,29.08 TP22.1 R67.1
MIPI_TX_DATA_LP_N3: length 11
  TOP w0.147: U1.AA5 49.51,27.46 49.51,26.65 48.26,25.4 44.7,25.4 v1(44.45,25.65)
  BOTTOM w0.147: v1(44.45,25.65) TP28.1 R46.2
MIPI_TX_DATA_LP_N4: length 11.2
  TOP w0.147: U1.AB6 50.7,26.65 50.7,26.32 48.64,24.26 44.32,24.26 v1(43.81,23.75)
  BOTTOM w0.147: R59.2 TP34.1 43.56,24 v1(43.81,23.75)
MIPI_TX_DATA_LP_P1: length 13.8
  TOP w0.147: U1.V5 v1(49.51,31.46)
  BOTTOM w0.147: v1(49.51,31.46) 49.01,31.97 47.21,31.97 46.61,31.37 44.96,31.37 44.83,31.5 44.83,31.88 44.96,32 45.7,32 45.85,32.15 45.85,32.49 45.7,32.64 44.7,32.64 44.45,32.89 44.45,33.66 TP13.1 R48.2
MIPI_TX_DATA_LP_P2: length 9.3
  TOP w0.147: U1.AB3 v1(47.51,26.46)
  BOTTOM w0.147: R60.2 TP19.1 43.31,29.46 43.31,28.45 44.83,26.92 45.09,26.92 45.59,27.43 45.85,27.43 46.31,26.97 47.01,26.97 v1(47.51,26.46)
MIPI_TX_DATA_LP_P3: length 11
  TOP w0.147: v1(44.45,24.77) 48.39,24.77 50.01,26.39 U1.AB5
  BOTTOM w0.147: R36.2 TP25.1 42.93,26.29 42.93,25.53 43.18,25.27 43.94,25.27 v1(44.45,24.77)
MIPI_TX_DATA_LP_P4: length 12.4
  TOP w0.147: U1.AB7 48.8,23.75 v1(44.45,23.75)
  BOTTOM w0.147: v1(44.45,23.75) 44.45,23.88 43.81,24.51 42.93,24.51 TP31.1 R49.2
MIPI_TX_GPIO1: length 23.1
  TOP w0.147: v1(47.51,32.46) 47.52,32.46 U1.U3
  ART04 w0.109: v2(39.37,18.8) 40.39,18.8 42.93,21.34 42.93,29.59 46.23,32.89 47.09,32.89 v1(47.51,32.46)
  BOTTOM w0.147: R273.1 37.02,18.73 37.47,18.29 38.86,18.29 v2(39.37,18.8)
MIPI_TX_GPIO1_IO: length 3.3
  BOTTOM w0.147: J1.10 34.86,21.15 36.13,19.88 R273.2
MIPI_TX_GPIO2: length 29.7
  TOP w0.147: R274.1 31.43,18.61 32.89,17.14 v2(35.18,17.14) ; U1.U2 v1(46.51,32.47)
  ART04 w0.109: v1(46.51,32.47) 45.09,31.04 45.09,27.43 45.97,26.54 45.97,23.75 39.37,17.14 v2(35.18,17.14)
MIPI_TX_GPIO2_IO: length 2.3
  TOP w0.147: R274.2 v2(29.72,20.07)
  BOTTOM w0.147: v2(29.72,20.07) 30.3,20.65 J1.9
MIPI_TX_GPIO3: length 35.7
  TOP w0.147: U1.U4 v1(48.51,31.46)
  ART04 w0.109: v1(48.51,31.46) 48.01,30.96 48.01,27.94 48.51,27.43 48.51,23.11 40.51,15.11 29.97,15.11 28.96,14.1 v2(28.32,14.1)
  BOTTOM w0.147: R275.1 27.3,15.49 27.94,14.86 27.94,14.48 v2(28.32,14.1)
MIPI_TX_GPIO3_IO: length 5.7
  BOTTOM w0.147: R275.2 28.57,16.83 29.34,17.59 29.34,18.96 30.02,19.65 J1.7
MIPI_TX_GPIO4: length 27.9
  TOP w0.147: U1.U5 49.52,32.46 v1(48.51,32.46)
  ART04 w0.109: v2(36.32,16) 36.83,16.51 39.62,16.51 46.99,23.88 46.99,28.7 46.48,29.21 46.48,31.37 46.99,31.88 47.93,31.88 v1(48.51,32.46)
  BOTTOM w0.147: R276.1 37.02,16.7 v2(36.32,16)
MIPI_TX_GPIO4_IO: length 3.2
  BOTTOM w0.147: R276.2 36.13,18.35 35.33,19.15 J1.6
MIPI_TX_GPIO5: length 33.6
  TOP w0.147: U1.V3 48.01,30.97 v1(47.52,31.47)
  ART04 w0.109: v1(47.52,31.47) 47.52,31.13 46.99,30.61 46.99,29.97 47.5,29.46 47.5,27.56 48.01,27.05 48.01,24 45.09,21.08 45.09,20.19 40.39,15.49 34.92,15.49 33.91,16.51 30.23,16.51 v2(29.59,15.88)
  BOTTOM w0.147: v2(29.59,15.88) 29.59,15.37 29.27,15.05 R277.1
MIPI_TX_GPIO5_IO: length 4.3
  BOTTOM w0.147: J1.5 29.99,18.65 29.72,18.38 29.72,17.08 R277.2
OV5640_CAM_PWRON: length 82
  TOP w0.137: v2(52.58,9.65) 52.68,9.76 J3.11
  TOP w0.147: U1.L2 46.51,38.47 40.91,38.47 40.13,39.24 35.94,39.24 35.18,38.48 34.42,38.48 31.11,35.18 31.11,33.4 30.48,32.77 30.48,29.97 29.72,29.21 v2(29.34,29.21)
  ART04 w0.109: v2(26.04,13.46) 26.92,12.57 29.21,12.57 30.61,13.97 40.89,13.97 44.58,17.65 44.83,17.65 v2(45.09,17.91)
  BOTTOM w0.147: v2(45.09,17.91) 45.6,17.91 45.85,17.66 45.85,16.76 48.64,13.97 52.07,13.97 53.44,12.6 53.44,11.53 52.58,10.67 v2(52.58,9.65) 51.7,9.65 C38.1 R98.2 ; v2(29.34,29.21) 28.83,28.7 28.83,26.54 25.53,23.24 25.53,13.97 v2(26.04,13.46)
OV5640_CAM_RESETB: length 35.1
  TOP w0.147: J3.15 54.68,11.86 54.61,11.94 v2(54.61,12.32) ; U1.M4 v1(48.51,36.46)
  ART04 w0.109: v2(47.5,19.43) 48.9,20.83 48.9,32.62 48.49,33.02 48.26,33.02 47.99,33.29 47.99,35.94 v1(48.51,36.46)
  BOTTOM w0.147: R99.2 55.18,10.79 55.13,10.85 C39.1 55.13,11.8 v2(54.61,12.32) 54.61,13.59 52.7,15.49 48.9,15.49 47.37,17.02 47.37,19.3 v2(47.5,19.43)
OV5640_CLK24MHZ: length 108.5
  TOP w0.147: v2(13.08,53.09) 14.22,51.94 v2(15.11,51.94) ; v2(52.96,12.32) 53.19,12.09 J3.12
  ART04 w0.109: v2(45.09,16.64) 44.58,16.64 41.4,13.46 30.86,13.46 29.46,12.07 26.42,12.07 25.27,13.21 25.27,19.18 23.88,20.57 21.46,20.57 20.95,21.08 20.95,21.72 18.67,24 14.48,24 13.34,25.15 13.34,32.26 8.76,36.83 8.76,41.15 6.86,43.05 6.1,43.05 2.54,46.61 v2(2.54,57.78)
  BOTTOM w0.147: v2(15.11,51.94) 15.05,52.01 R211.2 ; v2(52.96,12.32) 52.07,13.21 48.51,13.21 v2(45.09,16.64) ; v2(2.54,57.78) 10.29,57.78 12.06,56.01 12.06,54.1 v2(13.08,53.09)
OV5640_CLK24MHZ_R: length 2.9
  BOTTOM w0.147: U14.18 18.44,53.03 18.37,52.96 16.19,52.96 R211.1
OV5640_CLK_HS_N: length 26.4
  TOP w0.132: U1.V9 v1(54.51,30.46) ; R102.1 56.52,19.75 56.52,19.43 v1(56.26,19.18) 56.61,18.82 56.61,18.62 54.68,16.69 53.29,16.69 49.72,13.12 49.72,10.95 J3.5
  BOTTOM w0.132: v1(56.26,19.18) 56.61,19.53 56.61,19.9 R97.1 56.61,20.86 56.61,27.97 54.8,29.79 54.8,30.18 v1(54.51,30.46)
OV5640_CLK_HS_P: length 26.8
  TOP w0.132: R95.1 57.15,19.75 57.15,19.43 v1(57.4,19.18) 57.05,18.82 57.05,18.44 54.86,16.26 53.47,16.26 50.15,12.94 50.15,10.95 J3.6 ; U1.V10 v1(55.51,30.46)
  BOTTOM w0.132: v1(55.51,30.46) 55.23,30.18 55.23,29.97 55.74,29.46 56.13,29.46 56.39,29.21 56.39,28.81 57.05,28.15 57.05,27.56 57.28,27.33 57.28,26.92 57.05,26.7 57.05,20.86 R96.2 57.05,19.9 57.05,19.53 v1(57.4,19.18)
OV5640_CLK_LP_N: length 18.1
  TOP w0.147: R102.2 56.96,21.34 57.64,21.34 57.96,21.66 57.96,24.56 v1(58.17,24.77) ; U1.R14 v1(59.52,33.46)
  ART04 w0.109: v1(58.17,24.77) 58.17,25.53 58.04,25.65 58.04,27.3 58.17,27.43 58.55,27.43 58.67,27.3 58.67,26.44 58.82,26.29 59.16,26.29 59.31,26.44 59.31,27.94 59.05,28.19 59.05,33 v1(59.52,33.46)
OV5640_CLK_LP_P: length 18.5
  TOP w0.147: R95.2 57.85,20.76 58.29,21.21 58.29,24.26 v1(58.8,24.77) ; U1.R15 v1(60.52,33.46)
  ART04 w0.109: v1(60.52,33.46) 60.12,33.07 60.12,31.06 60.33,30.86 61.07,30.86 61.21,30.71 61.21,30.37 61.07,30.23 60.35,30.23 60.2,30.08 60.2,29.74 60.35,29.59 61.07,29.59 61.21,29.44 61.21,29.1 61.07,28.96 60.33,28.96 59.94,28.58 59.94,25.91 v1(58.8,24.77)
OV5640_DATA_HS_N1: length 25.2
  TOP w0.132: J3.8 51.22,10.95 51.22,12.86 52,13.64 53.29,13.64 53.67,14.02 53.67,14.68 54.41,15.42 56.21,15.42 59.28,18.5 59.28,18.82 v1(58.93,19.18) 59.34,19.59 59.34,19.97 R105.1 59.44,20.89 59.44,21.97 59.31,22.1 59.31,22.48 59.44,22.61 59.44,22.99 59.31,23.11 59.31,23.49 59.44,23.62 59.44,24 59.18,24.26 59.18,24.51 59.44,24.77 59.44,25.42 59.2,25.65 58.93,25.65 58.72,25.45 58.37,25.45 58.17,25.65 57.8,25.65 57.35,26.11 57.35,26.63 U1.AB12
  BOTTOM w0.132: v1(58.93,19.18) 59.18,19.43 59.18,19.75 R106.1
OV5640_DATA_HS_N2: length 24.7
  TOP w0.132: U1.AB10 55.29,26.69 55.29,26.06 53.92,24.69 53.92,20.84 R109.1 53.95,19.9 53.95,19.53 v1(53.59,19.18) 53.95,18.82 53.95,18.5 53.67,18.22 51.89,18.22 51.44,18.67 50.29,18.67 49.78,18.16 49.78,17.14 50.55,16.38 50.55,15.88 49.97,15.3 48.97,15.3 48.46,14.79 48.46,13.52 47.72,12.77 47.72,10.95 J3.1
  BOTTOM w0.132: v1(53.59,19.18) 53.85,19.43 53.85,19.75 R110.1
OV5640_DATA_HS_P1: length 24.5
  TOP w0.132: U1.AB13 57.78,26.73 57.78,26.29 57.98,26.09 59.38,26.09 59.87,25.6 59.87,20.84 R104.2 59.78,19.84 59.78,19.47 v1(60.07,19.18) 59.72,18.82 59.72,18.32 56.39,14.99 54.59,14.99 54.1,14.5 54.1,13.84 53.47,13.21 52.18,13.21 51.65,12.68 51.65,10.95 J3.9
  BOTTOM w0.132: R103.1 59.82,19.75 59.82,19.43 v1(60.07,19.18)
OV5640_DATA_HS_P2: length 25
  TOP w0.132: J3.2 48.15,10.95 48.15,12.59 48.9,13.34 48.9,14.61 49.15,14.86 50.15,14.86 50.98,15.69 50.98,16.56 50.22,17.33 50.22,17.98 50.47,18.23 51.25,18.23 51.71,17.78 53.85,17.78 54.38,18.32 54.38,18.82 v1(54.74,19.18) 54.38,19.53 54.38,19.9 R108.2 54.36,20.89 54.36,23.37 54.48,23.49 54.48,24 54.36,24.13 54.36,24.51 54.74,24.89 55.12,24.89 55.37,25.15 55.37,25.53 55.73,25.88 55.73,26.68 U1.AB11
  BOTTOM w0.132: R107.1 54.48,19.75 54.48,19.43 v1(54.74,19.18)
OV5640_DATA_LP_N1: length 14.4
  TOP w0.147: U1.W20 v1(64.51,30.47)
  ART04 w0.109: v1(64.51,30.47) 64.22,30.17 62.99,28.94 62.34,28.94 60.96,27.56 60.96,26.03 v1(60.33,25.4)
  BOTTOM w0.147: R106.2 59.63,21.34 60.45,21.34 60.83,21.72 60.83,22.73 59.82,23.75 59.82,24.89 v1(60.33,25.4)
OV5640_DATA_LP_N2: length 19.6
  TOP w0.147: U1.P14 v1(59.52,34.46)
  ART04 w0.109: v1(56.01,25.4) 56.52,25.4 56.99,25.88 56.99,33.05 56.39,33.66 56.39,34.16 56.69,34.46 v1(59.52,34.46)
  BOTTOM w0.147: R110.2 54.29,21.34 54.94,21.34 55.37,21.77 55.37,24.77 v1(56.01,25.4)
OV5640_DATA_LP_P1: length 13.3
  TOP w0.147: U1.W19 v1(64.52,29.46)
  ART04 w0.109: v1(64.52,29.46) 63.75,28.7 63.75,28.32 63.37,27.94 62.1,27.94 61.47,27.3 61.47,25.91 v1(60.33,24.77)
  BOTTOM w0.147: v1(60.33,24.77) 60.33,24 61.34,22.99 61.34,21.46 60.64,20.76 R103.2
OV5640_DATA_LP_P2: length 19.7
  TOP w0.147: U1.P15 v1(60.52,34.46)
  ART04 w0.109: v1(56.01,24.77) 56.64,24.77 57.47,25.59 57.47,27.62 58.04,28.19 58.04,28.7 58.19,28.85 58.4,28.85 58.55,29 58.55,29.29 58.4,29.44 58.19,29.44 58.04,29.59 58.04,29.88 58.19,30.03 58.4,30.03 58.55,30.18 58.55,30.47 58.4,30.62 58.19,30.62 58.04,30.77 58.04,33.66 58.42,34.04 60.09,34.04 v1(60.52,34.46)
  BOTTOM w0.147: v1(56.01,24.77) 56.01,22.97 55.65,22.61 55.65,21.61 54.8,20.76 R107.2
OV5640_SDA: length 81.3
  TOP w0.137: v2(54.36,9.65) 54.19,9.82 J3.14
  TOP w0.147: v2(29.34,28.45) 30.1,28.45 30.99,29.34 30.99,32.38 31.62,33.02 31.62,34.92 34.42,37.72 35.05,37.72 36.2,38.86 39.75,38.86 40.65,37.97 U1.L1
  ART04 w0.109: v2(46.61,18.8) 46.61,19.05 46.86,19.3 46.86,19.81 46.61,20.07 45.97,20.07 40.64,14.73 30.1,14.73 28.83,13.46 v2(27.81,13.46)
  BOTTOM w0.147: v2(27.81,13.46) 26.29,14.99 26.29,22.73 29.84,26.29 29.84,27.94 v2(29.34,28.45) ; v2(46.61,18.8) 46.61,18.54 46.99,18.16 46.99,16.81 48.82,14.99 52.45,14.99 54.1,13.34 54.1,11.18 54.36,10.92 v2(54.36,9.65) 54.36,8.95 R100.2
OV5640_SDC: length 81.2
  TOP w0.137: v2(53.47,9.65) 53.68,9.87 J3.13
  TOP w0.147: v2(29.34,27.69) 30.1,27.69 31.5,29.08 31.5,32 32.13,32.64 32.13,34.8 34.29,36.96 35.05,36.96 36.58,38.48 39.24,38.48 40.13,37.59 45.09,37.59 45.21,37.47 47.51,37.47 U1.M3
  ART04 w0.109: v2(26.92,13.46) 27.43,12.95 28.96,12.95 30.35,14.35 40.77,14.35 45.21,18.8 v2(45.85,18.8)
  BOTTOM w0.147: v2(26.92,13.46) 25.91,14.48 25.91,22.99 29.34,26.42 v2(29.34,27.69) ; R101.2 53.47,8.95 v2(53.47,9.65) 53.47,10.79 53.77,11.1 53.77,12.94 52.24,14.48 48.77,14.48 46.48,16.76 46.48,17.91 45.85,18.54 v2(45.85,18.8)
OV10640_24MHZ: length 41.8
  TOP w0.147: U1.N5 v1(49.51,36.46)
  ART04 w0.109: v1(49.51,36.46) 50.04,35.94 52.2,35.94 52.33,36.07 54.48,36.07 55.14,35.42 55.14,33.21 55.33,33.02 55.75,33.02 56.13,32.64 56.13,27.05 55.24,26.16 55.24,24.64 55.63,24.26 65.91,24.26 67.94,22.23 67.94,21.46 71.12,18.29 73.41,18.29 v2(73.91,17.78)
  BOTTOM w0.147: v2(73.91,17.78) 73.47,18.22 R94.2
OV10640_24MHZ_IO: length 4.8
  BOTTOM w0.147: J2.26 76.13,21.65 75.82,21.34 75.82,20.83 74.36,19.37 R94.1
OV10640_CLK_HS_N: length 30.5
  TOP w0.132: R77.1 73.72,29.97 74.04,29.97 v1(74.3,29.72) 74.71,30.14 75.65,30.14 77.14,28.65 78.54,28.65 v1(78.61,28.58) ; U1.R11 v1(55.51,33.46)
  BOTTOM w0.102: 67.82,33.74 67.74,33.83 58.85,33.83 58.67,33.65 58.17,33.65 57.99,33.83 57.02,33.83 56.84,33.66 56.52,33.66 56.34,33.83 55.88,33.83 v1(55.51,33.46)
  BOTTOM w0.132: 67.82,33.74 69.15,33.74 69.54,33.35 69.54,32.59 70.56,31.57 70.56,30.66 71.18,30.04 72.76,30.04 R75.1 73.67,30.04 73.97,30.04 v1(74.3,29.72) ; J2.12 77.6,28.91 78.28,28.91 v1(78.61,28.58)
OV10640_CLK_HS_P: length 30.3
  TOP w0.132: v1(78.61,29.21) 78.49,29.08 77.33,29.08 75.83,30.57 74.58,30.57 v1(74.3,30.86) 74.04,30.61 73.72,30.61 R71.1 ; U1.P11 v1(55.51,34.46)
  BOTTOM w0.102: v1(55.51,34.46) 55.89,34.09 67.74,34.09 67.82,34.18
  BOTTOM w0.132: v1(74.3,30.86) 73.91,30.48 73.72,30.48 R73.2 72.71,30.48 71.36,30.48 70.99,30.84 70.99,31.75 69.98,32.77 69.98,33.53 69.33,34.18 67.82,34.18 ; v1(78.61,29.21) 78.67,29.15 J2.11
OV10640_CLK_LP_N: length 11.4
  TOP w0.147: R77.2 72.97,29.58 72.97,29.08 72.85,28.96 72.39,28.96 72.14,29.21 71.88,29.21 71.63,28.96 71.25,28.96 70.99,28.7 69.85,28.7 69.72,28.83 69.72,29.21 69.98,29.46 69.98,29.84 69.72,30.1 69.72,30.61 v1(69.98,30.86) ; U1.T22 67.62,32.96 67.82,32.77 v1(67.82,32.46)
  BOTTOM w0.147: v1(67.82,32.46) 68.5,32.46 68.71,32.26 68.71,31.75 68.83,31.62 TP68.1 69.6,31.62 69.98,31.24 v1(69.98,30.86)
OV10640_CLK_LP_P: length 11.9
  TOP w0.147: v1(69.34,30.86) 70.1,31.62 70.36,31.62 70.61,31.37 71.12,31.37 71.37,31.62 72.52,31.62 72.71,31.43 R71.2 ; v1(66.52,32.46) 66.52,32.46 U1.T21
  BOTTOM w0.147: v1(69.34,30.86) 69.09,31.11 68.58,31.11 68.58,31.12 TP67.1 67.95,31.24 67.95,31.75 67.69,32 67.31,32 67.06,31.75 67.06,31.24 66.8,30.99 66.29,30.99 66.04,31.24 66.04,32.26 66.24,32.46 v1(66.52,32.46)
OV10640_CMOS_RST: length 64
  TOP w0.147: U1.P4 v1(48.51,34.46)
  ART04 w0.109: v1(48.51,34.46) 49.07,33.91 49.66,33.91 50.04,33.53 50.04,32.38 50.89,31.53 50.89,22.77 53.47,20.19 61.47,20.19 62.23,20.95 65.28,20.95 67.69,18.54 67.69,16.64 68.91,15.41 74.12,15.41 74.8,14.73 76.07,14.73 77.47,16.13 81.53,16.13 85.34,19.94 v2(85.34,22.86)
  BOTTOM w0.147: v2(85.34,22.86) 84.65,23.56 R91.2 83.31,23.56 83.26,23.5 C36.1 81.72,23.5 81.37,23.15 J2.23
